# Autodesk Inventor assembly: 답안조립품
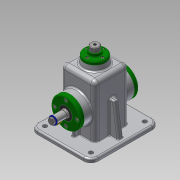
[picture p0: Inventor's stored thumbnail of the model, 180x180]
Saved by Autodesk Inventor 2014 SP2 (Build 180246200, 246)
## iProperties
Created: 2016-08
Part Number: 답안조립품
Document SubType Name: Assembly
Designer: user
Author: user
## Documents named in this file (19)
- C:\Users\user\Desktop\460820V1001\답안조립품.iam
- C:\Users\user\Desktop\460820V1001\본체.ipt
- C:\Users\user\Desktop\460820V1001\뒤커버.ipt
- C:\Users\user\Desktop\460820V1001\앞커버.ipt
- C:\Users\user\Desktop\460820V1001\상부부시.ipt
- C:\Users\user\Desktop\460820V1001\베어링 15 x 35 x 11.ipt
- C:\Users\user\Desktop\460820V1001\오일실 15 25 7.ipt
- C:\Users\user\Desktop\460820V1001\편심축.ipt
- C:\Users\user\Desktop\460820V1001\멈춤링 15 x 1.ipt
- C:\Users\user\Desktop\460820V1001\와셔.ipt
- C:\Users\user\Desktop\460820V1001\링크.ipt
- C:\Users\user\Desktop\460820V1001\슬라이드바.ipt
- C:\Users\user\Desktop\460820V1001\고정핀.ipt
- C:\Users\user\Desktop\460820V1001\멈춤링 6 x 5.ipt
- C:\Users\user\Desktop\460820V1001\키 5 x 5 x 14.ipt
- C:\Users\user\Desktop\460820V1001\V-벨트풀리.ipt
- C:\Users\user\Desktop\460820V1001\볼트 M6 x 12.ipt
- C:\Users\user\Desktop\460820V1001\볼트 M4 x 10.ipt
- C:\Users\user\Desktop\460820V1001\볼트 M3 x 8.ipt
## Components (15 placed, 5 different names)
1. 고정핀:1
2. V-벨트풀리:1 — 각도:1
3. ISO 4018 M6 x 12:1 — 강체:2
4. ISO 4762 M4 x 10:1 — 강체:3
5. ISO 4762 M4 x 10:3
6. ISO 4762 M4 x 10:4
7. ISO 4762 M4 x 10:5
8. ISO 4762 M4 x 10:2 — 강체:4
9. ISO 4762 M4 x 10:6
10. ISO 4762 M4 x 10:7
11. ISO 4762 M4 x 10:8
12. ISO 4762 M3 x 8:1 — 강체:5
13. ISO 4762 M3 x 8:2
14. ISO 4762 M3 x 8:3
15. ISO 4762 M3 x 8:4
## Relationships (5: WeldJoint 4, Angle 1)
- 각도:1 [Angle]: V-벨트풀리:1
- 강체:2 [WeldJoint]: ISO 4018 M6 x 12:1
- 강체:3 [WeldJoint]: ISO 4762 M4 x 10:1
- 강체:4 [WeldJoint]: ISO 4762 M4 x 10:2
- 강체:5 [WeldJoint]: ISO 4762 M3 x 8:1
